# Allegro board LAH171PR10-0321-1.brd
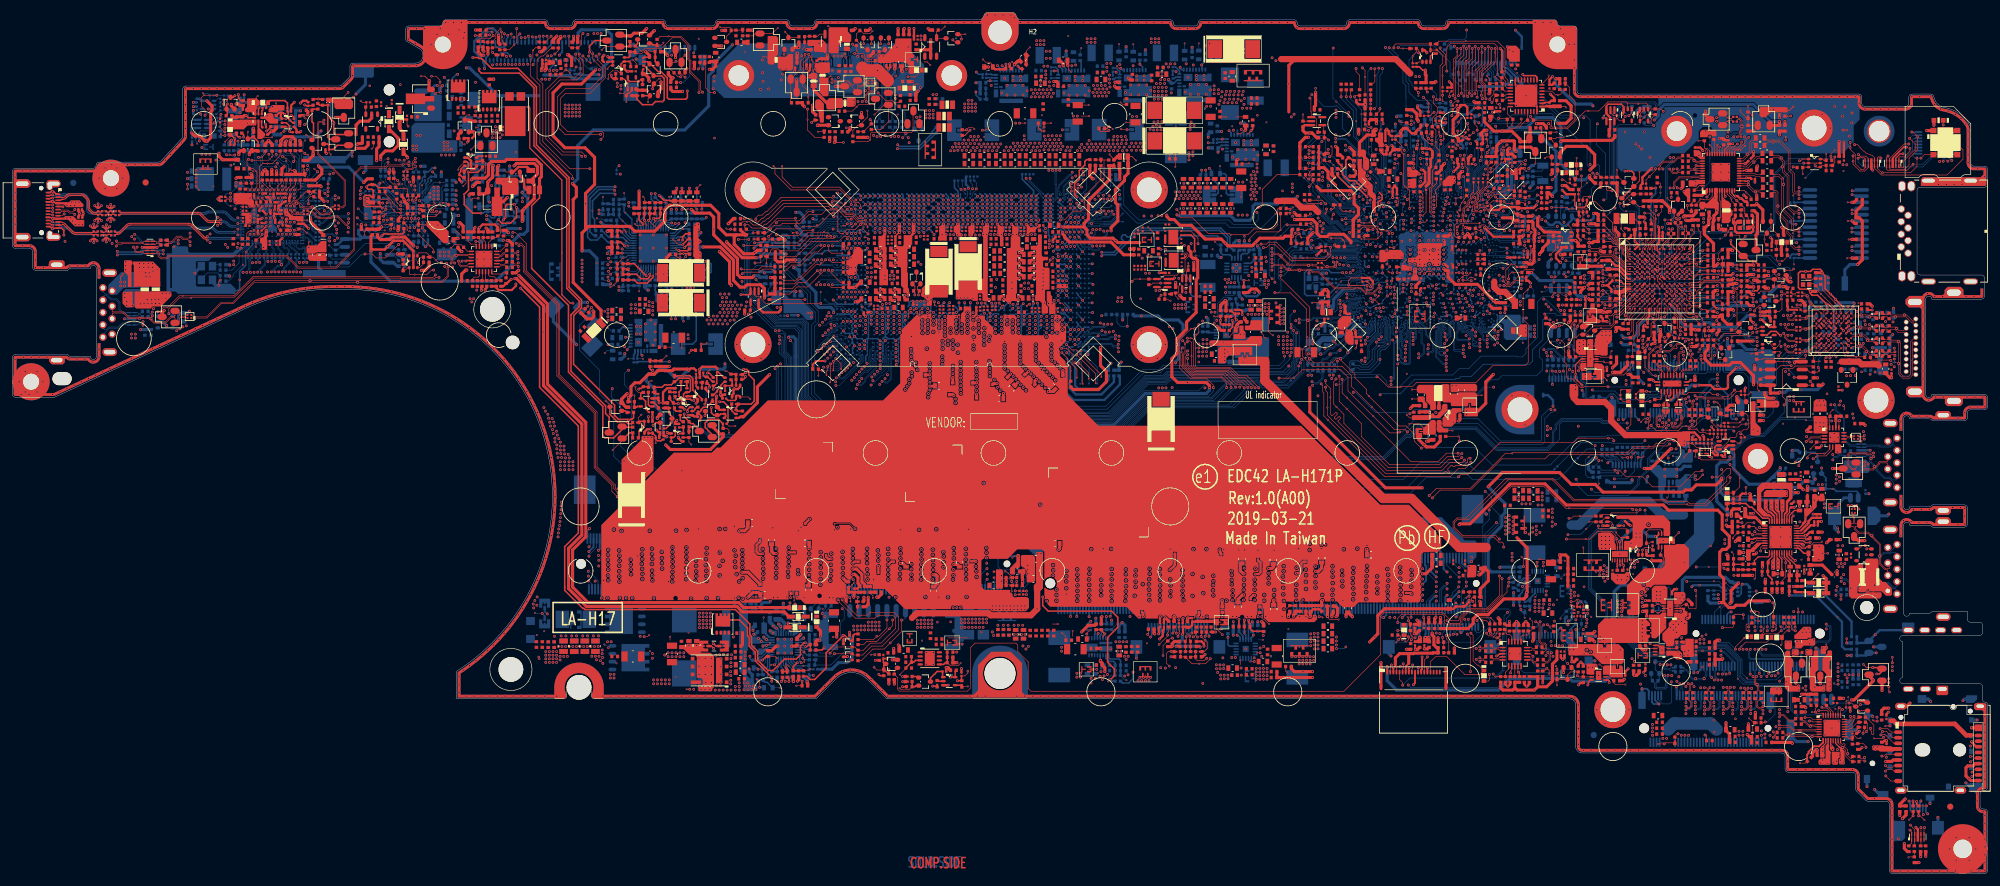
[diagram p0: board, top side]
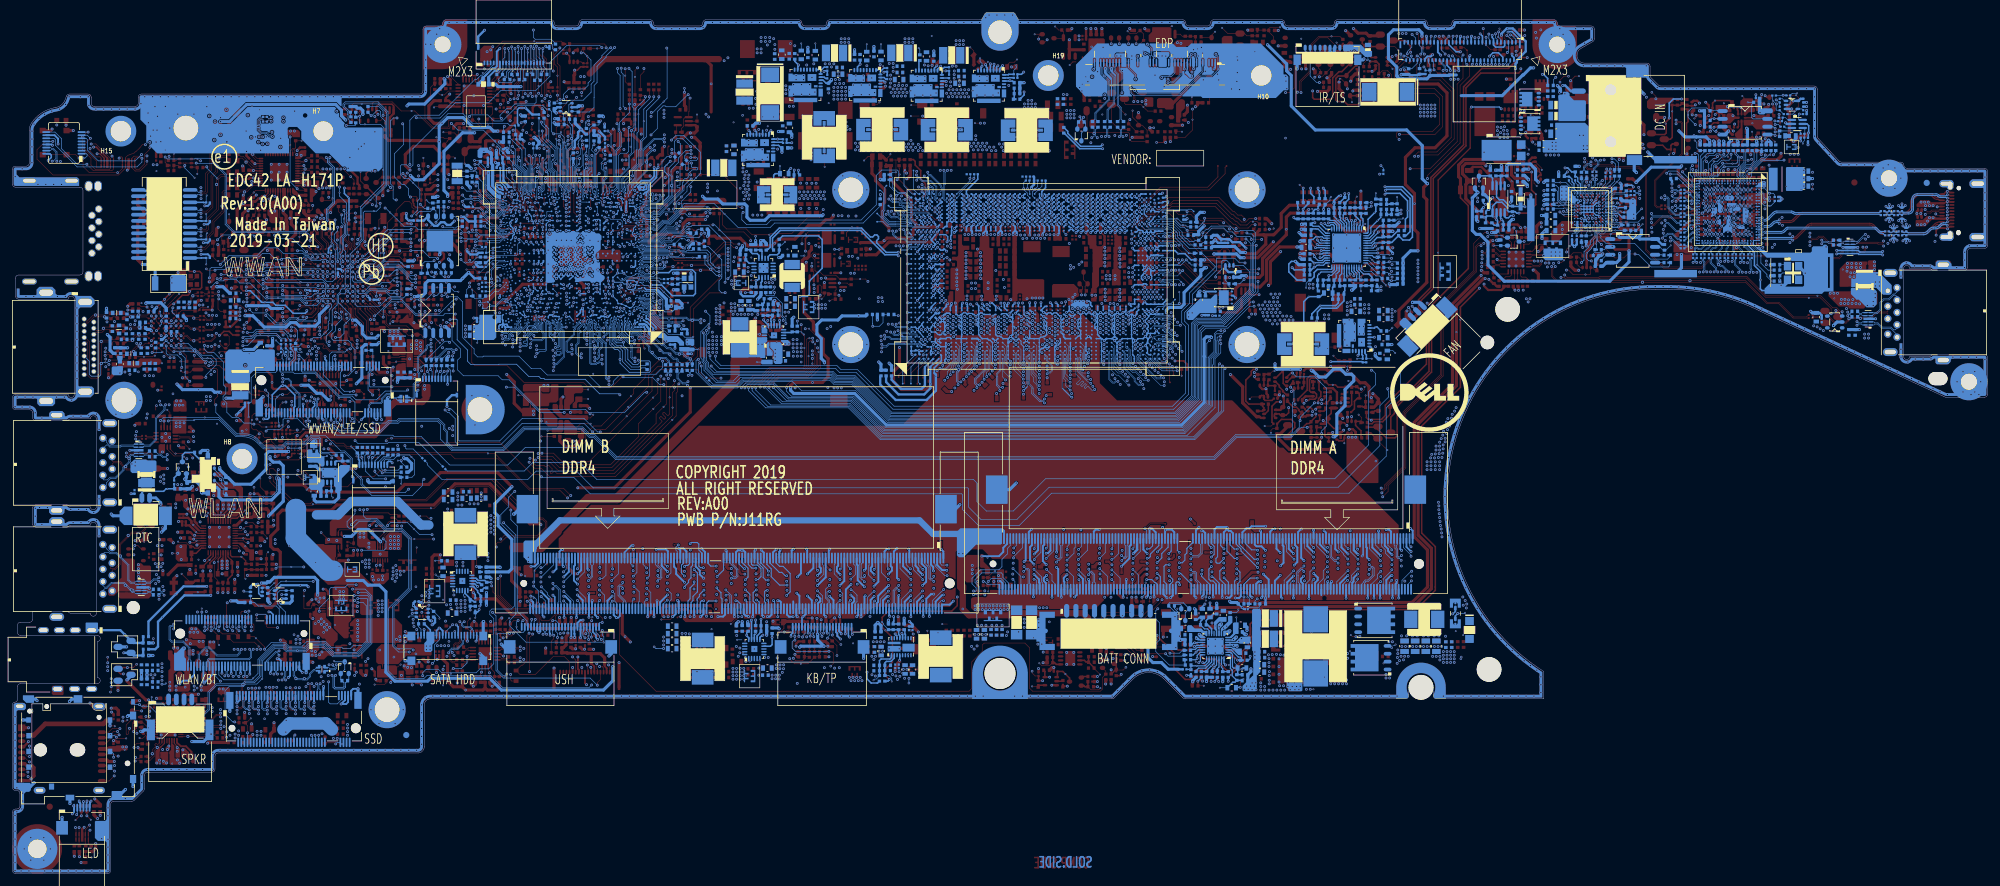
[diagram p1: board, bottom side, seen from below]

Outline 319.05 x 139.2 mm; copper layers: TOP, GND1, IN1, VCC, IN2, IN3, GND2, IN4, GND3, BOTTOM. Coordinates in mm from the lower left corner of the outline.

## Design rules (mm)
net group DDR_A_CLK0: nets DDR_A_CLK0 DDR_A_CLK#0
net group DDR_A_CLK1: nets DDR_A_CLK1 DDR_A_CLK#1
net group DDR_A_DQS0: nets DDR_A_DQS0 DDR_A_DQS#0
net group DDR_A_DQS1: nets DDR_A_DQS1 DDR_A_DQS#1
net group DDR_A_DQS2: nets DDR_A_DQS2 DDR_A_DQS#2
net group DDR_A_DQS3: nets DDR_A_DQS3 DDR_A_DQS#3
net group DDR_A_DQS4: nets DDR_A_DQS4 DDR_A_DQS#4
net group DDR_A_DQS5: nets DDR_A_DQS5 DDR_A_DQS#5
net group DDR_A_DQS6: nets DDR_A_DQS6 DDR_A_DQS#6
net group DDR_A_DQS7: nets DDR_A_DQS7 DDR_A_DQS#7
net group DDR_ALERT: nets DDR_A_ALERT# DDR_B_ALERT#
net group DDR_B_CLK0: nets DDR_B_CLK0 DDR_B_CLK#0
net group DDR_B_CLK1: nets DDR_B_CLK1 DDR_B_CLK#1
net group DDR_B_DQS0: nets DDR_B_DQS0 DDR_B_DQS#0
net group DDR_B_DQS1: nets DDR_B_DQS1 DDR_B_DQS#1
net group DDR_B_DQS2: nets DDR_B_DQS2 DDR_B_DQS#2
net group DDR_B_DQS3: nets DDR_B_DQS3 DDR_B_DQS#3
net group DDR_B_DQS4: nets DDR_B_DQS4 DDR_B_DQS#4
net group DDR_B_DQS6: nets DDR_B_DQS6 DDR_B_DQS#6
net group DDR_B_DQS7: nets DDR_B_DQS7 DDR_B_DQS#7
net group DDR_REST: nets DDR4_DRAMRST#_PCH DDR_DRAMRST#
net group DDRA_CKE: nets DDR_A_CKE0 DDR_A_CKE1
net group DDRB_CKE: nets DDR_B_CKE0 DDR_B_CKE1
net group SD_1_DAT0: nets SD_1_DAT0 SD_1_DAT1
net group SD_1_DAT0_R: nets SD_1_DAT0_R SD_1_DAT1_R
net group TBTA_LS: nets TBTA_LSRX TBTA_LSTX
net group TBTA_SBU: nets TBTA_SBU1 TBTA_SBU2
net group UPD1_SMBCLK: nets UPD1_SMBCLK UPD1_SMBDAT
net group UPD1_SMBCLK_Q: nets UPD1_SMBCLK_Q UPD1_SMBDAT_Q
net group VSSMPHY_SENSE: nets VCCMPHY_SENSE VSSMPHY_SENSE
net group 5: nets ESPI_ALERT# ESPI_CS# ESPI_IO0 ESPI_IO0_R ESPI_IO1 ESPI_IO1_R ESPI_IO2 ESPI_IO2_R ESPI_IO3 ESPI_IO3_R ESPI_RESET# PCH_SPI_CS#0 PCH_SPI_CS#0_R1 PCH_SPI_CS#0_R2 PCH_SPI_CS#1 PCH_SPI_CS#1_R1 PCH_SPI_CS#1_R3 PCH_SPI_CS#2 PCH_SPI_CS#2_R PCH_SPI_D0 PCH_SPI_D0_0_R PCH_SPI_D0_1_R PCH_SPI_D0_2_R PCH_SPI_D0_R1 PCH_SPI_D1 PCH_SPI_D1_0_R PCH_SPI_D1_1_R PCH_SPI_D1_2_R PCH_SPI_D1_R1 PCH_SPI_D2 PCH_SPI_D2_0_R PCH_SPI_D2_1_R PCH_SPI_D2_R1 PCH_SPI_D2_XDP PCH_SPI_D3 PCH_SPI_D3_0_R PCH_SPI_D3_1_R PCH_SPI_D3_R1
net group 10: nets H_THERMTRIP# PCH_RTCRST# SYS_RESET#
net group 12: nets BC_CLK_ECE1117 BC_DAT_ECE1117 PCIECOMP PCIECOMP# SD_1_CLK SD_1_CLK_R
net group 14: nets I2C1_SCK_TP
net group 15: nets AUD_AZACPU_SCLK AUD_AZACPU_SCLK_R CLK_TP_SIO_R CPU_XDP_TCLK DAT_TP_SIO_I2C_CLK DAT_TP_SIO_R DMIC_CLK0 DMIC_CLK_CODEC DPSNK0_DDC_CLK ESPI_CLK ESPI_CLK_5105 GPU_SMCLK HDA_BIT_CLK HDA_BIT_CLK_R I2C0_SCL_TS I2C1_SCK_TP_R LSPCON_CLK MEM_SMBCLK MSCLK PBAT_CHARGER_SMBCLK PBAT_SMBCLK_C PCH_CL_CLK1 PCH_CL_DATA1 PCH_CL_RST1# PCH_DP1_CTRL_CLK PCH_DP3_CTRL_CLK PCH_JTAGX PCH_SPI_CLK PCH_SPI_CLK_0_R PCH_SPI_CLK_1_R PCH_SPI_CLK_2_R PCH_SPI_CLK_R1 PCI_CLK_LPC1 PCIE_WAKE#_AR PCIE_WAKE#_AR_R SCL_CHG SML0_SMBCLK SML1_SMBCLK SUSCLK SUSCLK_R SVID_ALERT#_PWR_CPU SVID_DAT_PWR_CPU TBT_I2C_SCL TBT_ROM_CLK TBT_RTD3_WAKE# TBT_RTD3_WAKE#_GPD7 TBT_RTD3_WAKE#_K18 TBTA_ROM_CLK_PD TBTA_ROM_CLK_PD_R USB2_COMP WIGIG_32KHZ
net group 20: nets HDMI_CLK_27M_IN HDMI_CLK_27M_OUT HDMI_CLK_27M_OUT_R MEC_XTAL1 MEC_XTAL2 MEC_XTAL2_R PCH_RTCX1 PCH_RTCX1_R PCH_RTCX2 REFCLK_CNV XCLK_RBIAS XTAL24_IN XTAL24_IN_R1 XTAL24_OUT XTAL24_OUT_R1 XTAL_25_IN XTAL_25_IN_R XTAL_25_OUT XTAL_25_OUT_R XTALI XTALO XTALO_R
net group 25: nets EDP_COMP
net group CARD READER: nets SD_1_N0 SD_1_N1 SD_1_P0 SD_1_P1
net group CNVI: nets CLK_CNV_PRX_DTX_N CLK_CNV_PRX_DTX_P CLK_CNV_PTX_DRX_N CLK_CNV_PTX_DRX_P CNV_PRX_DTX_N0 CNV_PRX_DTX_N1 CNV_PRX_DTX_P0 CNV_PRX_DTX_P1 CNV_PTX_DRX_N0 CNV_PTX_DRX_N1 CNV_PTX_DRX_P0 CNV_PTX_DRX_P1
net group DDR_RCOMP: nets DDR_RCOMP0 DDR_RCOMP1 DDR_RCOMP2
net group DDR_XDP_WAN_SMBCLK: nets DDR_XDP_WAN_SMBDAT
net group DDRA_CMD: nets DDR_A_ACT# DDR_A_BA0 DDR_A_BA1 DDR_A_BG0 DDR_A_BG1 DDR_A_MA0 DDR_A_MA1 DDR_A_MA2 DDR_A_MA3 DDR_A_MA4 DDR_A_MA5 DDR_A_MA6 DDR_A_MA7 DDR_A_MA8 DDR_A_MA9 DDR_A_MA10 DDR_A_MA11 DDR_A_MA12 DDR_A_MA13 DDR_A_MA14 DDR_A_MA15 DDR_A_MA16 DDR_A_PAR
net group DDRA_CTL: nets DDR_A_CS#0 DDR_A_CS#1 DDR_A_ODT0 DDR_A_ODT1
net group DDRA_D0: nets DDR_A_D0 DDR_A_D1 DDR_A_D2 DDR_A_D3 DDR_A_D4 DDR_A_D5 DDR_A_D6 DDR_A_D7
net group DDRA_D1: nets DDR_A_D8 DDR_A_D9 DDR_A_D10 DDR_A_D11 DDR_A_D12 DDR_A_D13 DDR_A_D14 DDR_A_D15
net group DDRA_D2: nets DDR_A_D16 DDR_A_D17 DDR_A_D18 DDR_A_D19 DDR_A_D20 DDR_A_D21 DDR_A_D22 DDR_A_D23
net group DDRA_D3: nets DDR_A_D24 DDR_A_D25 DDR_A_D26 DDR_A_D27 DDR_A_D28 DDR_A_D29 DDR_A_D30 DDR_A_D31
net group DDRA_D4: nets DDR_A_D32 DDR_A_D33 DDR_A_D34 DDR_A_D35 DDR_A_D36 DDR_A_D37 DDR_A_D38 DDR_A_D39
net group DDRA_D5: nets DDR_A_D40 DDR_A_D41 DDR_A_D42 DDR_A_D43 DDR_A_D44 DDR_A_D45 DDR_A_D46 DDR_A_D47
net group DDRA_D6: nets DDR_A_D48 DDR_A_D49 DDR_A_D50 DDR_A_D51 DDR_A_D52 DDR_A_D53 DDR_A_D54 DDR_A_D55
net group DDRA_D7: nets DDR_A_D56 DDR_A_D57 DDR_A_D58 DDR_A_D59 DDR_A_D60 DDR_A_D61 DDR_A_D62 DDR_A_D63
net group DDRB_CMD: nets DDR_B_ACT# DDR_B_BA0 DDR_B_BA1 DDR_B_BG0 DDR_B_BG1 DDR_B_MA0 DDR_B_MA1 DDR_B_MA2 DDR_B_MA3 DDR_B_MA4 DDR_B_MA5 DDR_B_MA6 DDR_B_MA7 DDR_B_MA8 DDR_B_MA9 DDR_B_MA10 DDR_B_MA11 DDR_B_MA12 DDR_B_MA13 DDR_B_MA14 DDR_B_MA15 DDR_B_MA16 DDR_B_PAR
net group DDRB_CTL: nets DDR_B_CS#0 DDR_B_CS#1 DDR_B_ODT0 DDR_B_ODT1
net group DDRB_D0: nets DDR_B_D0 DDR_B_D1 DDR_B_D2 DDR_B_D3 DDR_B_D4 DDR_B_D5 DDR_B_D6 DDR_B_D7
net group DDRB_D1: nets DDR_B_D8 DDR_B_D9 DDR_B_D10 DDR_B_D11 DDR_B_D12 DDR_B_D13 DDR_B_D14 DDR_B_D15
net group DDRB_D2: nets DDR_B_D16 DDR_B_D17 DDR_B_D18 DDR_B_D19 DDR_B_D20 DDR_B_D21 DDR_B_D22 DDR_B_D23
net group DDRB_D3: nets DDR_B_D24 DDR_B_D25 DDR_B_D26 DDR_B_D27 DDR_B_D28 DDR_B_D29 DDR_B_D30 DDR_B_D31
net group DDRB_D4: nets DDR_B_D32 DDR_B_D33 DDR_B_D34 DDR_B_D35 DDR_B_D36 DDR_B_D37 DDR_B_D38 DDR_B_D39
net group DDRB_D5: nets DDR_B_D40 DDR_B_D41 DDR_B_D42 DDR_B_D43 DDR_B_D44 DDR_B_D45 DDR_B_D46 DDR_B_D47
net group DDRB_D6: nets DDR_B_D48 DDR_B_D49 DDR_B_D50 DDR_B_D51 DDR_B_D52 DDR_B_D53 DDR_B_D54 DDR_B_D55
net group DDRB_D7: nets DDR_B_D56 DDR_B_D57 DDR_B_D58 DDR_B_D59 DDR_B_D60 DDR_B_D61 DDR_B_D62 DDR_B_D63
net group DMI: nets DMI_CRX_PTX_N0 DMI_CRX_PTX_N1 DMI_CRX_PTX_N2 DMI_CRX_PTX_N3 DMI_CRX_PTX_P0 DMI_CRX_PTX_P1 DMI_CRX_PTX_P2 DMI_CRX_PTX_P3 DMI_CTX_PRX_N0 DMI_CTX_PRX_N1 DMI_CTX_PRX_N2 DMI_CTX_PRX_N3 DMI_CTX_PRX_P0 DMI_CTX_PRX_P1 DMI_CTX_PRX_P2 DMI_CTX_PRX_P3
net group DP: nets CPU_DP1_AUXN CPU_DP1_AUXN_C CPU_DP1_AUXP CPU_DP1_AUXP_C CPU_DP1_N0 CPU_DP1_N0_C CPU_DP1_N1 CPU_DP1_N1_C CPU_DP1_N2 CPU_DP1_N2_C CPU_DP1_N3 CPU_DP1_N3_C CPU_DP1_P0 CPU_DP1_P0_C CPU_DP1_P1 CPU_DP1_P1_C CPU_DP1_P2 CPU_DP1_P2_C CPU_DP1_P3 CPU_DP1_P3_C CPU_DP2_AUXN CPU_DP2_AUXN_C CPU_DP2_AUXP CPU_DP2_AUXP_C CPU_DP2_N0 CPU_DP2_N0_C CPU_DP2_N1 CPU_DP2_N1_C CPU_DP2_N2 CPU_DP2_N2_C CPU_DP2_N3 CPU_DP2_N3_C CPU_DP2_P0 CPU_DP2_P0_C CPU_DP2_P1 CPU_DP2_P1_C CPU_DP2_P2 CPU_DP2_P2_C CPU_DP2_P3 CPU_DP2_P3_C CPU_DP3_AUXN CPU_DP3_AUXN_C CPU_DP3_AUXN_R CPU_DP3_AUXP CPU_DP3_AUXP_C CPU_DP3_AUXP_R CPU_DP3_N0 CPU_DP3_N0_C CPU_DP3_N1 CPU_DP3_N1_C CPU_DP3_N2 CPU_DP3_N2_C CPU_DP3_N3 CPU_DP3_N3_C CPU_DP3_P0 CPU_DP3_P0_C CPU_DP3_P1 CPU_DP3_P1_C CPU_DP3_P2 CPU_DP3_P2_C CPU_DP3_P3 CPU_DP3_P3_C
net group EDP: nets EDP_AUXN EDP_AUXN_C EDP_AUXP EDP_AUXP_C EDP_TXN0 EDP_TXN0_C EDP_TXN1 EDP_TXN1_C EDP_TXP0 EDP_TXP0_C EDP_TXP1 EDP_TXP1_C
net group HDA: nets AUD_AZACPU_SDI AUD_AZACPU_SDI_R AUD_AZACPU_SDO AUD_AZACPU_SDO_R DMIC0 HDA_RST# HDA_RST#_R HDA_SDIN0 HDA_SDIN0_R HDA_SDOUT HDA_SDOUT_R HDA_SYNC HDA_SYNC_R
net group HDMI: nets HDMI_CTRL_CLK HDMI_CTRL_DATA HDMI_L_CLKN HDMI_L_CLKP HDMI_L_TX_N0 HDMI_L_TX_N1 HDMI_L_TX_N2 HDMI_L_TX_P0 HDMI_L_TX_P1 HDMI_L_TX_P2 HDMI_LS_CLKN HDMI_LS_CLKP HDMI_LS_TX_N0 HDMI_LS_TX_N1 HDMI_LS_TX_N2 HDMI_LS_TX_P0 HDMI_LS_TX_P1 HDMI_LS_TX_P2
net group I2C: nets CLK_TP_SIO_I2C_DAT I2C0_SDA_TS I2C1_SDA_TP I2C1_SDA_TP_R TBT_I2C_SDA
net group LAN: nets LAN_MDIN0 LAN_MDIN0_L LAN_MDIN1 LAN_MDIN1_L LAN_MDIN2 LAN_MDIN2_L LAN_MDIN3 LAN_MDIN3_L LAN_MDIP0 LAN_MDIP0_L LAN_MDIP1 LAN_MDIP1_L LAN_MDIP2 LAN_MDIP2_L LAN_MDIP3 LAN_MDIP3_L
net group PCIE: nets PCIE_PRX_C_DTX_N5 PCIE_PRX_C_DTX_N6 PCIE_PRX_C_DTX_P5 PCIE_PRX_C_DTX_P6 PCIE_PRX_C_TTX_N1 PCIE_PRX_C_TTX_N2 PCIE_PRX_C_TTX_N3 PCIE_PRX_C_TTX_N4 PCIE_PRX_C_TTX_P1 PCIE_PRX_C_TTX_P2 PCIE_PRX_C_TTX_P3 PCIE_PRX_C_TTX_P4 PCIE_PRX_DTX_N5 PCIE_PRX_DTX_N6 PCIE_PRX_DTX_N7 PCIE_PRX_DTX_N9 PCIE_PRX_DTX_N10 PCIE_PRX_DTX_N11 PCIE_PRX_DTX_N12 PCIE_PRX_DTX_N17 PCIE_PRX_DTX_N18 PCIE_PRX_DTX_P5 PCIE_PRX_DTX_P6 PCIE_PRX_DTX_P7 PCIE_PRX_DTX_P9 PCIE_PRX_DTX_P10 PCIE_PRX_DTX_P11 PCIE_PRX_DTX_P12 PCIE_PRX_DTX_P17 PCIE_PRX_DTX_P18 PCIE_PRX_L_DTX_N18 PCIE_PRX_L_DTX_P18 PCIE_PRX_SW_DTX_N18 PCIE_PRX_SW_DTX_P18 PCIE_PRX_TTX_N1 PCIE_PRX_TTX_N2 PCIE_PRX_TTX_N3 PCIE_PRX_TTX_N4 PCIE_PRX_TTX_P1 PCIE_PRX_TTX_P2 PCIE_PRX_TTX_P3 PCIE_PRX_TTX_P4 PCIE_PTX_C_DRX_N5 PCIE_PTX_C_DRX_N6 PCIE_PTX_C_DRX_N7 PCIE_PTX_C_DRX_N9 PCIE_PTX_C_DRX_N10 PCIE_PTX_C_DRX_N11 PCIE_PTX_C_DRX_N12 PCIE_PTX_C_DRX_N17 PCIE_PTX_C_DRX_P5 PCIE_PTX_C_DRX_P6 PCIE_PTX_C_DRX_P7 PCIE_PTX_C_DRX_P9 PCIE_PTX_C_DRX_P10 PCIE_PTX_C_DRX_P11 PCIE_PTX_C_DRX_P12 PCIE_PTX_C_DRX_P17 PCIE_PTX_C_SW_DRX_N18 PCIE_PTX_C_SW_DRX_P18 PCIE_PTX_C_TRX_N1 PCIE_PTX_C_TRX_N2 PCIE_PTX_C_TRX_N3 PCIE_PTX_C_TRX_N4 PCIE_PTX_C_TRX_P1 PCIE_PTX_C_TRX_P2 PCIE_PTX_C_TRX_P3 PCIE_PTX_C_TRX_P4 PCIE_PTX_DRX_N5 PCIE_PTX_DRX_N6 PCIE_PTX_DRX_N7 PCIE_PTX_DRX_N9 PCIE_PTX_DRX_N10 PCIE_PTX_DRX_N11 PCIE_PTX_DRX_N12 PCIE_PTX_DRX_N17 PCIE_PTX_DRX_N18 PCIE_PTX_DRX_P5 PCIE_PTX_DRX_P6 PCIE_PTX_DRX_P7 PCIE_PTX_DRX_P9 PCIE_PTX_DRX_P10 PCIE_PTX_DRX_P11 PCIE_PTX_DRX_P12 PCIE_PTX_DRX_P17 PCIE_PTX_DRX_P18 PCIE_PTX_L_DRX_N18 PCIE_PTX_L_DRX_P18 PCIE_PTX_SW_DRX_N18 PCIE_PTX_SW_DRX_P18 PCIE_PTX_TRX_N1 PCIE_PTX_TRX_N2 PCIE_PTX_TRX_N3 PCIE_PTX_TRX_N4 PCIE_PTX_TRX_P1 PCIE_PTX_TRX_P2 PCIE_PTX_TRX_P3 PCIE_PTX_TRX_P4
net group PECI: nets H_PECI PCH_PECI PECI_EC_R
net group PLATFORM CLK: nets CLK_PCIE_N0 CLK_PCIE_N1 CLK_PCIE_N3 CLK_PCIE_N4 CLK_PCIE_N5 CLK_PCIE_N6 CLK_PCIE_P0 CLK_PCIE_P1 CLK_PCIE_P3 CLK_PCIE_P4 CLK_PCIE_P5 CLK_PCIE_P6 CPU_24MHZ_R_D CPU_24MHZ_R_D# PCH_CPU_BCLK_D PCH_CPU_BCLK_D# PCH_CPU_BCLK_R_D PCH_CPU_BCLK_R_D# PCH_CPU_NSSC_CLK_D PCH_CPU_NSSC_CLK_D# PCH_CPU_PCIBCLK_D PCH_CPU_PCIBCLK_D# PCH_CPU_PCIBCLK_R_D PCH_CPU_PCIBCLK_R_D# PCH_XDP_CLK_DN PCH_XDP_CLK_DN_R PCH_XDP_CLK_DP PCH_XDP_CLK_DP_R
net group RJ45: nets RJ45_MDIN0 RJ45_MDIN1 RJ45_MDIN2 RJ45_MDIN3 RJ45_MDIP0 RJ45_MDIP1 RJ45_MDIP2 RJ45_MDIP3
net group S12: nets CPU_2_PCH_TRIGGER CPU_2_PCH_TRIGGER_R DGPU_HOLD_RST# H_CATERR# H_PM_DOWN H_PM_DOWN_R H_PM_SYNC H_PM_SYNC_R H_PROCHOT#_R H_THERMTRIP#_R PCH_2_CPU_TRIGGER PCH_2_CPU_TRIGGER_R PCH_PLTRST# PCH_PLTRST#_AND PCH_TBT_PERST# PCH_THERMTRIP# PLTRST_LAN# PLTRST_TPM# PROCHOT# PROCHOT#_CHG PROCHOT#_R1 TBT_PERST# TBT_PERST#_R TBT_RESET_N_EC TBT_RESET_N_EC_R TBTA_RESET_N_EC_R THERMTRIP1# THERMTRIP2# VCCST_PWRGD VCCST_PWRGD_CPU VRHOT#_CPU XDP_OBS0 XDP_OBS0_R XDP_OBS1 XDP_OBS1_R
net group S15: nets H_VCCST_PWRGD_XDP PCH_DPWROK PCH_DPWROK_EC PCH_INTRUDER_HDR# PCH_PCIE_WAKE# PCH_PWROK PCH_RSMRST# PCH_RSMRST#_AND PCIE_WAKE# PCIE_WAKE#_R SRTCRST# SYS_PWROK
net group S20: nets +DDR_VREF_A_CA +DDR_VREF_B_CA +DDR_VREF_B_DQ +DDR_VREF_CA
net group SATA: nets SATA_PRX_C_DTX_N2 SATA_PRX_C_DTX_P2 SATA_PRX_C_RD_DTX_N2 SATA_PRX_C_RD_DTX_P2 SATA_PRX_DTX_N2 SATA_PRX_DTX_P2 SATA_PRX_RD_DTX_N2 SATA_PRX_RD_DTX_P2 SATA_PTX_C_DRX_N2 SATA_PTX_C_DRX_P2 SATA_PTX_C_RD_DRX_N2 SATA_PTX_C_RD_DRX_P2 SATA_PTX_DRX_N2 SATA_PTX_DRX_P2 SATA_PTX_RD_DRX_N2 SATA_PTX_RD_DRX_P2
net group SD: nets SD_1_CD# SD_1_CMD SD_1_CMD_R SD_1_DAT2 SD_1_DAT2_R SD_1_DAT3 SD_1_DAT3_R
net group SENSE: nets VCC_SENSE_GT VCC_SENSE_IA VCC_SENSE_SA VCCIO_SENSE VSS_SENSE_GT VSS_SENSE_IA VSS_SENSE_SA VSSIO_SENSE
net group SIO: nets H_PWRGD PLTRST_CPU# SIO_EXT_SMI# SIO_EXT_WAKE# SIO_EXT_WAKE#_EC SIO_PWRBTN# SIO_RCIN# SIO_SLP_A# SIO_SLP_LAN# SIO_SLP_S0# SIO_SLP_S3# SIO_SLP_S4#_R SIO_SLP_S5# SIO_SLP_SUS# SIO_SLP_SUS#_R SIO_SLP_WLAN# SYS_PWROK_R XDP_DBRESET#
net group SMB: nets DDR_XDP_WAN_SMBCLK DDR_XDP_WAN_SMBCLK_XDP DDR_XDP_WAN_SMBDAT_XDP SML1_SMBDATA USH_EXPANDER_SMBCLK USH_EXPANDER_SMBDAT
net group SPK: nets INT_SPK_L+ INT_SPK_L- INT_SPK_R+ INT_SPK_R-
net group SVID: nets CPU_VIDALERT# VR_SVID_ALERT# VR_SVID_CLK VR_SVID_DATA
net group TBT: nets TBT_A_TRX_C_DTX_N0 TBT_A_TRX_C_DTX_N1 TBT_A_TRX_C_DTX_P0 TBT_A_TRX_C_DTX_P1 TBT_A_TRX_DTX_N0 TBT_A_TRX_DTX_N1 TBT_A_TRX_DTX_P0 TBT_A_TRX_DTX_P1 TBT_A_TRX_R_DTX_N0 TBT_A_TRX_R_DTX_N1 TBT_A_TRX_R_DTX_P0 TBT_A_TRX_R_DTX_P1 TBT_A_TTX_C_DRX_N0 TBT_A_TTX_C_DRX_N1 TBT_A_TTX_C_DRX_P0 TBT_A_TTX_C_DRX_P1 TBT_A_TTX_DRX_N0 TBT_A_TTX_DRX_N1 TBT_A_TTX_DRX_P0 TBT_A_TTX_DRX_P1 TBT_A_TTX_R_DRX_N0 TBT_A_TTX_R_DRX_N1 TBT_A_TTX_R_DRX_P0 TBT_A_TTX_R_DRX_P1
net group TBT-S: nets SW_TBT_A_USB20_N1 SW_TBT_A_USB20_N1_R SW_TBT_A_USB20_N2 SW_TBT_A_USB20_N2_R SW_TBT_A_USB20_P1 SW_TBT_A_USB20_P1_R SW_TBT_A_USB20_P2 SW_TBT_A_USB20_P2_R TBTA_AUXN TBTA_AUXN_C TBTA_AUXP TBTA_AUXP_C TBTA_LSRX_R TBTA_LSTX_R TBTA_SBU1_R TBTA_SBU2_R
net group THERMAL: nets REM_DIODE1_N REM_DIODE1_P REM_DIODE2_N REM_DIODE2_P REM_DIODE4_N REM_DIODE4_P
net group UART: nets CNV_BRI_PRX_DTX CNV_BRI_PRX_DTX_R CNV_BRI_PTX_DRX CNV_BRI_PTX_DRX_R CNV_RGI_PRX_DTX CNV_RGI_PRX_DTX_R CNV_RGI_PTX_DRX CNV_RGI_PTX_DRX_R ISH_UART0_CTS#_R ISH_UART0_RXD_R ISH_UART0_TXD_R LPSS_UART2_RXD
net group UIM: nets UIM_CLK UIM_DATA UIM_RESET
net group USB20: nets CHR_USB20_N1 CHR_USB20_N1_R CHR_USB20_P1 CHR_USB20_P1_R TBTA_USB20_N TBTA_USB20_N_R TBTA_USB20_P TBTA_USB20_P_R USB20_N1 USB20_N2 USB20_N2_R USB20_N3 USB20_N3_R USB20_N4 USB20_N4_FP USB20_N4_USH USB20_N5 USB20_N6 USB20_N8 USB20_N8_R USB20_N10 USB20_N11 USB20_N11_R USB20_N14 USB20_N14_R USB20_P1 USB20_P2 USB20_P2_R USB20_P3 USB20_P3_R USB20_P4 USB20_P4_FP USB20_P4_USH USB20_P5 USB20_P6 USB20_P8 USB20_P8_R USB20_P10 USB20_P11 USB20_P11_R USB20_P14 USB20_P14_R
net group USB30: nets USB3_PRX_C_RD_DTX_N3 USB3_PRX_C_RD_DTX_P3 USB3_PRX_DTX_N1 USB3_PRX_DTX_N2 USB3_PRX_DTX_N3 USB3_PRX_DTX_N4 USB3_PRX_DTX_P1 USB3_PRX_DTX_P2 USB3_PRX_DTX_P3 USB3_PRX_DTX_P4 USB3_PRX_RD_DTX_N3 USB3_PRX_RD_DTX_P3 USB3_PTX_C_DRX_N1 USB3_PTX_C_DRX_N2 USB3_PTX_C_DRX_N3 USB3_PTX_C_DRX_N4 USB3_PTX_C_DRX_P1 USB3_PTX_C_DRX_P2 USB3_PTX_C_DRX_P3 USB3_PTX_C_DRX_P4 USB3_PTX_C_RD_DRX_N3 USB3_PTX_C_RD_DRX_P3 USB3_PTX_DRX_N1 USB3_PTX_DRX_N2 USB3_PTX_DRX_N3 USB3_PTX_DRX_N4 USB3_PTX_DRX_P1 USB3_PTX_DRX_P2 USB3_PTX_DRX_P3 USB3_PTX_DRX_P4 USB3_PTX_RD_DRX_N3 USB3_PTX_RD_DRX_P3
nets with their own width: min track width 0.254; nets +3.3V_TBT_FLASH_R +COINCELL +RTC_CELL +Z4012 AUD_HP_NB_SENSE AUD_SENSE_A BAT1_LED# BAT1_LED#_R BAT2_LED# BATT_WHITE# BATT_YELLOW# CNV_WT_RCOMP GPPJ_RCOMP PEG_COMP SD_RCOMP_1P8 SD_RCOMP_3P3 TBTA_CC1 TBTA_CC2
nets with their own width: min track width 0.381; nets +3.3V_EC_PLL +LINE1-VREFO-L +LINE1-VREFO-R +VSS_PLL AUD_HP_OUT_L AUD_HP_OUT_L1 AUD_HP_OUT_R AUD_HP_OUT_R1 HP_OUT_L HP_OUT_R LINE1_L LINE1_R
nets with their own width: min track width 0.508; nets +1.0V_ALW_PCH +1.0V_AMPHYPLL +1.0V_AZPLL +1.0V_BCLKPLL2 +1.0V_CLPLLEBB +1.0V_DSW +1.0V_DUSB +1.0V_MPHY +1.0V_OC +1.0V_OCPLL1 +1.0V_PRIM_CNV_HVLO +1.0V_PRIM_FUSE +1.0V_PRIM_XDP +1.0V_SRC +1.0V_VCCSFR +1.0V_VCCSFR_R +1.0V_VCCST +1.0V_VCCST_C +1.0V_VCCSTG +1.0V_VCCSTG_C +1.0V_XTAL +1.0VS_VCCIO +1.2V_LDO +1.2V_LSPCON_VDD +1.2V_LSPCON_VDDA +1.2V_LSPCON_VDDRX +1.2V_LSPCON_VDDTX +1.2V_RUN +1.8V_ALW_VTR3 +1.8V_RUN +1.8V_RUN_CARD +1.8V_RUN_UZ8 +2.8V_FHV0 +2.8V_FHV1 +3.3V_1.8V_AZIO +3.3V_1.8V_GPPA +3.3V_1.8V_GPPD +3.3V_1.8V_SPI +3.3V_ALW +3.3V_ALW2 +3.3V_ALW_UE1 +3.3V_CAM +3.3V_DSW +3.3V_FPBTN +3.3V_FUSE +3.3V_LAN_OUT +3.3V_LSPCON +3.3V_LSPCON_VDD +3.3V_MMI_AUX +3.3V_PGPPBC +3.3V_PGPPEF +3.3V_PGPPG +3.3V_PGPPHK +3.3V_PHVC +3.3V_PUSB2 +3.3V_RTC_LDO +3.3V_RUN +3.3V_RUN_AUDIO +3.3V_RUN_AUDIO_DVDD +3.3V_RUN_AUDIO_IO +3.3V_RUN_DIMM2 +3.3V_SPI +3.3V_TBT_LC +3.3V_TBT_SX +3.3V_TBTA_FLASH +3.3V_TP +3.3V_VDD_DCIN +3.3V_VDD_PIC +3.3V_VPS_UZ12 +5V_ALW +5V_ALW2 +5V_PD_VDD +5V_TBT_VBUS +5V_TBTA_VBUS_D +EC_DEBUG_VCC +RSVD_VCC3P3_1 +RTC_CELL_PCH +SIM_PWR +VCC_FUSEPRG +VCC_SFR_OC +VDDA_AVDD1 GND GNDA
nets with their own width: min track width 0.762; nets +0.9V_LAN +2.5V_MEM +3.3V_VDD_PIC_PDA
nets with their own width: min track width 1.016; nets +3.3V_LAN +3.3V_LAN_UZ2 +3.3V_RUN_CARD +TS_PWR +VHDMI_VCC INT_SPKR_L+ INT_SPKR_L- INT_SPKR_R+ INT_SPKR_R-
nets with their own width: min track width 1.143; nets +3.3V_PHVLDO
nets with their own width: min track width 1.27; nets +1.8V_PRIM +1.8V_PRIM_PCH +3.3V_MMI_IN +MIC2-VREFO RING2 RING2_R SLEEVE SLEEVE_R
nets with their own width: min track width 1.524; nets +3.3V_TBT +3.3V_TBT_S0 +5V_HDD +EDP_VDD +LCDVDD
nets with their own width: min track width 2.032; nets +0.6V_DDR_VTT +3.3V_SSD +BL_PWR_SRC +USB_EX2_PWR +USB_EX3_PWR
nets with their own width: min track width 2.286; nets +3.3V_HDD +3.3V_HDD_M2 +3.3V_WLAN
nets with their own width: min track width 2.54; nets +3.3V_WLAN_UZ4 +5V_RUN_AUDIO +5V_RUN_PVDD_L +5V_USB_CHG_PWR
nets with their own width: min track width 2.794; nets +3.3V_WWAN +3.3V_WWAN_UZ2
nets with their own width: min track width 3.048; nets +5V_ALW_PDA +20V_TBTA_VBUS
nets with their own width: min track width 3.302; nets +3.3V_ALW_PCH +3.3V_ALW_PCH_UZ3
nets with their own width: min track width 4.572; nets +5V_RUN +5V_RUN_UZ4

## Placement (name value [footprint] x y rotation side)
CA1  220P_0402_50V7K  [C_0402]  297.31 30.54 90 bottom
CA2  680P_0402_50V7K  [C_0402]  297.04 37.28 0 bottom
CA3  680P_0402_50V7K  [C_0402]  297.04 35.25 0 bottom
CA4  220P_0402_50V7K  [C_0402]  297.31 33.74 270 bottom
CA5  27P_0402_50V8J  [C_0402]  128.54 124.59 180 top
CA6  82P_0402_50V8J  [C_0402]  125.84 124.59 0 top
CA7  0.1U_0201_10V6K  [C_0201]  128.88 130.76 180 top
CA8  0.1U_0201_10V6K  [C_0201]  289.43 49.72 270 top
CA9  10U_0603_10V6M  [C_0603]  290.38 49.87 270 top
CA10  0.1U_0201_10V6K  [C_0201]  280.67 57.64 90 top
CA12  680P_0402_50V7K  [C_0402]  298.2 30.54 90 bottom
CA13  680P_0402_50V7K  [C_0402]  298.2 32.83 90 bottom
CA19  1000P_0402_50V7K  [C_0402]  283.21 60.21 90 top
CA22  1000P_0402_50V7K  [C_0402]  285.87 60.21 90 top
CA23  1000P_0402_50V7K  [C_0402]  284.98 60.21 90 top
CA24  1000P_0402_50V7K  [C_0402]  284.09 60.21 90 top
CA25  10U_0603_10V6M  [C_0603]  285.87 48.46 180 top
CA27  0.1U_0402_25V6  [C_0402]  281.36 49.16 90 top
CA28  0.1U_0402_25V6  [C_0402]  279.51 50 0 top
CA29  1U_0201_6.3V6K  [C_0201]  292.1 58.1 270 top
CA31  1U_0201_6.3V6M  [C_0201]  279.01 59.84 90 top
CA33  10P_0402_50V8J  [C_0402]  278.71 55.14 180 top
CA35  2.2U_0402_6.3V6M  [C_0402]  290.24 52.86 0 top
CA41  0.1U_0402_25V6  [C_0402]  283.6 50.24 180 top
CA43  10U_0603_10V6M  [C_0603]  288.41 49.62 270 top
CA44  10U_0603_10V6M  [C_0603]  287.14 49.62 270 top
CA45  0.1U_0201_10V6K  [C_0201]  287.36 61.59 0 top
CA46  10U_0603_10V6M  [C_0603]  282.13 60.6 180 top
CA47  0.1U_0201_10V6K  [C_0201]  281.97 59.71 180 top
CA48  10U_0603_10V6M  [C_0603]  287.21 62.63 0 top
CA49  1U_0201_6.3V6K  [C_0201]  291.63 56.28 180 top
CA51  10U_0603_10V6M  [C_0603]  290.13 51.78 0 top
CA52  10U_0603_10V6M  [C_0603]  288.67 58.7 90 top
CA53  10U_0603_10V6M  [C_0603]  280.35 54.06 180 top
CA54  100P_0402_50V8J  [C_0402]  278.71 56.09 180 top
CA55  0.1U_0201_10V6K  [C_0201]  281.17 52.19 270 top
CA56  10U_0603_10V6M  [C_0603]  280.35 51.9 180 top
CA57  0.1U_0201_10V6K  [C_0201]  287.27 59.2 90 top
CA58  10U_0603_10V6M  [C_0603]  289.87 58.7 90 top
CA59  10U_0603_10V6M  [C_0603]  289.81 64.84 270 top
CA60  0.1U_0201_10V6K  [C_0201]  288.86 64.88 270 top
CA61  10U_0603_10V6M  [C_0603]  279.92 57.94 180 top
CA62  100P_0402_50V8J  [C_0402]  278.01 50 180 top
CA63  12P_0402_50V8J  [C_0402]  288.03 64.62 270 top
CA64  68P_0402_50V8J  [C_0402]  287.14 64.62 270 top
CA65  12P_0402_50V8J  [C_0402]  261.87 33.68 270 top
CA66  68P_0402_50V8J  [C_0402]  262.76 33.68 270 top
CA67  12P_0402_50V8J  [C_0402]  281.29 73.23 0 top
CA68  68P_0402_50V8J  [C_0402]  281.29 74.11 0 top
CA69  33P_0402_50V8J  [C_0402]  291.14 61.03 90 top
CA72  100P_0402_50V8J  [C_0402]  280.41 49.12 270 top
CA73  2P_0402_50V8C  [C_0402]  218.38 120.28 180 top
CA74  2P_0402_50V8C  [C_0402]  221.24 121.87 180 top
CA75  2P_0402_50V8C  [C_0402]  218.49 121.87 0 top
CA76  2P_0402_50V8C  [C_0402]  219.4 125.04 180 top
CA77  330P_0402_50V8J  [C_0402]  290.37 54.25 0 top
CA78  330P_0402_50V8J  [C_0402]  290.75 55.19 0 top
CA79  1U_0201_6.3V6K  [C_0201]  291.46 58.1 270 top
CA80  1U_0201_6.3V6K  [C_0201]  291.63 56.92 180 top
CC28  0.1U_0402_25V6  [C_0402]  89.42 131.52 0 top
CC29  0.1U_0402_25V6  [C_0402]  89.42 130.63 0 top
CC32  0.1U_0201_10V6K  [C_0201]  90.8 129.82 270 bottom
CC33  0.1U_0402_25V6  [C_0402]  90.42 133.47 90 top
CC81  22U_0603_6.3V6M  [C_0603]  150.41 78.83 180 top
CC82  22U_0603_6.3V6M  [C_0603]  167.39 79.22 315 top
CC83  22U_0603_6.3V6M  [C_0603]  158.66 76.78 0 top
CC84  22U_0603_6.3V6M  [C_0603]  160.9 77.94 45 top
CC161  10U_0402_6.3V6M  [C_0402]  155.74 75.94 90 top
CC163  10U_0402_6.3V6M  [C_0402]  164.15 80.01 135 top
CC164  10U_0402_6.3V6M  [C_0402]  154.2 79.32 0 top
CC165  10U_0402_6.3V6M  [C_0402]  150.47 77.42 0 top
CC166  10U_0402_6.3V6M  [C_0402]  151.89 78.4 90 top
CC167  10U_0402_6.3V6M  [C_0402]  165.8 78.41 135 top
CC168  10U_0402_6.3V6M  [C_0402]  160.07 79.57 45 top
CC170  10U_0402_6.3V6M  [C_0402]  157.44 79.07 0 top
CC171  10U_0402_6.3V6M  [C_0402]  146.54 80.59 0 top
CC172  10U_0402_6.3V6M  [C_0402]  154.08 91.34 180 top
CC185  10U_0402_6.3V6M  [C_0402]  169.67 79.63 90 top
CC186  1U_0201_6.3V6M  [C_0201]  181.22 97.64 90 top
CC187  10U_0402_6.3V6M  [C_0402]  168.97 95.84 270 top
CC188  10U_0402_6.3V6M  [C_0402]  168.07 97.36 180 top
CC189  10U_0402_6.3V6M  [C_0402]  168.07 96.47 180 top
CC191  1U_0201_6.3V6M  [C_0201]  182.56 104.43 270 top
CC192  1U_0201_6.3V6M  [C_0201]  169.07 102.94 180 top
CC193  1U_0201_6.3V6M  [C_0201]  181.24 103.44 270 top
CC194  1U_0201_6.3V6M  [C_0201]  181.81 104 270 top
CC195  1U_0201_6.3V6M  [C_0201]  181.8 97.64 90 top
CC209  1U_0201_6.3V6M  [C_0201]  137.54 90.69 0 top
CC210  1U_0201_6.3V6M  [C_0201]  125.77 90.27 90 bottom
CC269  0.1U_0402_25V6  [C_0402]  87.32 133.45 90 top
CC272  10U_0402_6.3V6M  [C_0402]  168.07 95.58 180 top
CC300  100P_0402_50V8J  [C_0402]  129.17 103.2 180 bottom
CC301  100P_0402_50V8J  [C_0402]  178.42 90.37 0 bottom
CC302  0.1U_0402_25V6  [C_0402]  211.91 118.95 180 top
CC303  0.1U_0402_25V6  [C_0402]  208.58 103.53 0 bottom
CC304  0.1U_0402_25V6  [C_0402]  208.33 101.86 0 top
CC305  0.1U_0402_25V6  [C_0402]  212.16 101.67 180 bottom
CC306  0.1U_0402_25V6  [C_0402]  91.75 130.11 270 bottom
CC307  0.1U_0402_25V6  [C_0402]  85.97 134.39 270 top
CC308  0.1U_0402_25V6  [C_0402]  93.52 130.08 270 bottom
CC310  0.1U_0201_10V6K  [C_0201]  221.94 116.25 0 top
CC311  0.1U_0201_10V6K  [C_0201]  212.85 86.09 270 bottom
CC316  33P_0402_50V8J  [C_0402]  248.85 82.1 90 bottom
CC318  33P_0402_50V8J  [C_0402]  228.44 116.49 270 bottom
CC319  33P_0402_50V8J  [C_0402]  228.39 119.83 0 top
CC320  33P_0402_50V8J  [C_0402]  229.92 121.08 0 bottom
CC322  2.2P_0402_50V8C  [C_0402]  126.34 92.45 90 bottom
CC323  0.1U_0402_25V6  [C_0402]  174.94 115.4 270 top
CC324  0.1U_0402_25V6  [C_0402]  126.29 102.88 180 bottom
CC325  33P_0402_50V8J  [C_0402]  117.61 105.86 180 top
CC327  2.2P_0402_50V8C  [C_0402]  222.11 117.04 0 top
CC328  2.2P_0402_50V8C  [C_0402]  240.28 92.29 270 top
CC329  0.1U_0201_10V6K  [C_0201]  221.19 118.41 0 top
CC330  0.1U_0201_10V6K  [C_0201]  209.99 84.6 270 bottom
CC331  0.1U_0201_10V6K  [C_0201]  216.37 87.32 0 top
CC332  0.1U_0201_10V6K  [C_0201]  217.8 86.14 90 top
CC333  22U_0603_6.3V6M  [C_0603]  178.81 114.63 0 top
CC334  0.1U_0201_10V6K  [C_0201]  86.2 130.88 180 top
CC335  0.1U_0201_10V6K  [C_0201]  86.2 131.52 180 top
CC336  0.1U_0201_10V6K  [C_0201]  123.82 101.95 90 bottom
CC337  0.1U_0201_10V6K  [C_0201]  122.68 101.95 90 bottom
CC500  10U_0402_6.3V6M  [C_0402]  168.07 94.69 180 top
CC501  10U_0402_6.3V6M  [C_0402]  168.91 98.17 90 top
CC549  0.1U_0201_10V6K  [C_0201]  129.92 106.28 270 bottom
CC556  0.1U_0201_10V6K  [C_0201]  241.93 114.91 90 top
CC557  0.1U_0201_10V6K  [C_0201]  182.37 98.22 270 top
CC558  0.1U_0201_10V6K  [C_0201]  182.94 98.22 270 top
CC568  22U_0603_6.3V6M  [C_0603]  127.4 93.44 270 bottom
CC569  22U_0603_6.3V6M  [C_0603]  184.22 100.67 180 top
CD1  10U_0603_6.3V6M  [C_0603]  148.78 44.99 90 top
CD2  10U_0603_6.3V6M  [C_0603]  120.2 56.68 180 top
CD3  10U_0603_6.3V6M  [C_0603]  122.61 54.64 270 top
CD4  10U_0603_6.3V6M  [C_0603]  122.23 45.06 180 top
CD5  10U_0603_6.3V6M  [C_0603]  128.58 45.16 90 top
CD6  10U_0603_6.3V6M  [C_0603]  127.31 53.37 0 top
CD7  10U_0603_6.3V6M  [C_0603]  153 51 270 top
CD8  10U_0603_6.3V6M  [C_0603]  144.36 51 270 top
CD9  1U_0201_10V6M  [C_0201]  126.95 51.91 180 top
CD10  1U_0201_10V6M  [C_0201]  154.9 51.08 270 top
CD11  1U_0201_10V6M  [C_0201]  128.08 55.96 90 top
CD12  1U_0201_10V6M  [C_0201]  120.77 54.47 270 top
CD13  1U_0201_10V6M  [C_0201]  136.69 51.01 270 top
CD14  1U_0201_10V6M  [C_0201]  131.44 52.03 270 top
CD15  1U_0201_10V6M  [C_0201]  139.89 48.03 90 top
CD16  1U_0201_10V6M  [C_0201]  142.38 51.01 270 top
CD17  1U_0201_10V6M  [C_0201]  165.55 48.84 180 top
CD18  1U_0201_10V6M  [C_0201]  165.55 49.79 180 top
CD19  10U_0603_6.3V6M  [C_0603]  166.01 50.87 180 top
CD20  10U_0603_6.3V6M  [C_0603]  165.67 47.64 180 top
CD21  330U_D3_2.5VY_R6M  [C_D3]  100.01 58.02 90 top
CD22  10U_0603_6.3V6M  [C_0603]  159.19 46.58 180 top
CD23  1U_0201_10V6M  [C_0201]  159.14 48.8 180 top
CD24  1U_0201_10V6M  [C_0201]  159.14 47.85 180 top
CD25  0.1U_0201_6.3V6K  [C_0201]  135.95 45.49 90 top
CD26  2.2U_0402_6.3V6M  [C_0402]  136.84 45.49 90 top
CD27  2.2U_0402_6.3V6M  [C_0402]  162.44 49.92 0 top
CD28  0.1U_0201_10V6K  [C_0201]  162.55 50.68 0 top
CD29  0.1U_0402_25V6  [C_0402]  120.13 43.6 0 bottom
CD31  0.022U_0402_16V7K  [C_0402]  138.55 46.4 270 top
CD32  0.1U_0402_25V6  [C_0402]  121.68 46.77 180 top
CD33  10U_0603_6.3V6M  [C_0603]  211.48 51.68 270 top
CD34  10U_0603_6.3V6M  [C_0603]  220.18 51.56 180 top
CD35  10U_0603_6.3V6M  [C_0603]  215.74 43.62 270 top
CD36  10U_0603_6.3V6M  [C_0603]  197.99 42.43 90 top
CD37  10U_0603_6.3V6M  [C_0603]  203.74 42.03 90 top
CD38  10U_0603_6.3V6M  [C_0603]  203.67 51.43 270 top
CD39  10U_0603_6.3V6M  [C_0603]  198.59 51.56 270 top
CD40  10U_0603_6.3V6M  [C_0603]  167.76 53.35 0 top
CD41  1U_0201_10V6M  [C_0201]  200.02 43.79 90 top
CD42  1U_0201_10V6M  [C_0201]  225.1 44.78 90 top
CD43  1U_0201_10V6M  [C_0201]  201.2 51.32 270 top
CD44  1U_0201_10V6M  [C_0201]  208.88 51 270 top
CD45  1U_0201_10V6M  [C_0201]  195.87 51.62 180 top
CD46  1U_0201_10V6M  [C_0201]  187.76 52.28 270 top
CD47  1U_0201_10V6M  [C_0201]  192.25 42.29 180 top
CD48  1U_0201_10V6M  [C_0201]  181.88 42.29 0 top
CD49  330U_D3_2.5VY_R6M  [C_D3]  185.54 70.28 90 top
CD50  1U_0201_10V6M  [C_0201]  232.74 50.62 270 top
CD51  1U_0201_10V6M  [C_0201]  234.64 50.61 270 top
CD52  10U_0603_6.3V6M  [C_0603]  230.72 51.43 180 top
CD53  10U_0603_6.3V6M  [C_0603]  230.72 50.16 180 top
CD54  10U_0603_6.3V6M  [C_0603]  232.09 42.81 90 top
CD55  1U_0201_10V6M  [C_0201]  234.31 43.18 90 top
CD56  1U_0201_10V6M  [C_0201]  233.17 43.18 90 top
CD57  0.1U_0201_6.3V6K  [C_0201]  210.53 43.32 270 top
CD58  2.2U_0402_6.3V6M  [C_0402]  211.48 43.32 270 top
CD59  2.2U_0402_6.3V6M  [C_0402]  235.24 48.19 180 top
CD60  0.1U_0201_10V6K  [C_0201]  235.27 48.95 180 top
CD61  0.1U_0402_25V6  [C_0402]  195.42 42.21 90 top
CD62  0.022U_0402_16V7K  [C_0402]  207.23 42.4 90 top
CE3  2200P_0402_50V7K  [C_0402]  258.05 92.91 0 top
CE4  2200P_0402_50V7K  [C_0402]  256.6 112.55 270 top
CE8  .047U_0402_16V7K  [C_0402]  279.26 94.94 0 top
CE10  0.1U_0201_10V6K  [C_0201]  263.88 111.52 180 top
CE11  0.1U_0201_10V6K  [C_0201]  262.04 103.21 180 top
CE12  2.2U_0402_6.3V6M  [C_0402]  263.01 109.85 90 top
CE13  0.1U_0201_10V6K  [C_0201]  261.29 92.76 180 bottom
CE14  1U_0201_10V6M  [C_0201]  265.97 103.05 0 top
CE15  0.1U_0201_10V6K  [C_0201]  259.01 95.88 180 top
CE16  10U_0402_6.3V6M  [C_0402]  251.68 100.1 180 top
CE17  22U_0603_6.3V6M  [C_0603]  257.76 99.11 270 top
CE18  0.1U_0201_10V6K  [C_0201]  258.99 98.26 270 top
CE19  0.1U_0201_10V6K  [C_0201]  280.73 90.35 270 top
CE20  0.1U_0201_10V6K  [C_0201]  266.47 97.14 90 bottom
CE21  0.1U_0201_10V6K  [C_0201]  264.14 88.91 270 top
CE22  0.1U_0201_10V6K  [C_0201]  256.31 89.29 0 top
CE23  0.1U_0201_10V6K  [C_0201]  265.97 103.68 0 top
CE24  2200P_0402_50V7K  [C_0402]  268.37 103.43 180 top
CE25  0.1U_0201_10V6K  [C_0201]  270.34 94.18 0 bottom
CE26  2200P_0402_50V7K  [C_0402]  269.52 105.21 180 top
CE27  2200P_0402_50V7K  [C_0402]  270.72 103.49 180 top
CE28  12P_0402_50V8J  [C_0402]  260.38 103.21 180 top
CE29  12P_0402_50V8J  [C_0402]  262.82 105.22 90 top
CE30  1U_0201_10V6M  [C_0201]  276.18 96.72 0 top
CE31  1U_0201_10V6M  [C_0201]  258.87 94.03 180 top
CE32  10U_0402_6.3V6M  [C_0402]  92.39 88.34 225 top
CE35  100P_0402_50V8J  [C_0402]  146.48 94.18 180 top
CE36  0.1U_0402_25V6  [C_0402]  284.74 89.99 180 top
CE37  100P_0402_50V8J  [C_0402]  265.82 31.19 180 bottom
CE38  0.1U_0402_25V6  [C_0402]  273.86 100.78 0 top
CE39  100P_0402_50V8J  [C_0402]  146.84 121.49 180 bottom
CE40  4700P_0402_25V7K  [C_0402]  276.21 95.07 0 top
CE46  100P_0402_50V8J  [C_0402]  131.35 43.28 0 bottom
CE47  4700P_0402_25V7K  [C_0402]  274.77 88.78 270 top
CE52  0.1U_0402_25V6K  [C_0402]  258.83 119.26 180 top
CE53  0.1U_0402_25V6K  [C_0402]  258.83 120.22 180 top
CE54  10P_0402_50V8J  [C_0402]  255.14 98.11 90 bottom
CE57  33P_0402_50V8J  [C_0402]  282.05 96.59 0 top
CE59  12P_0402_50V8J  [C_0402]  253.87 100.52 90 top
CE60  68P_0402_50V8J  [C_0402]  276.21 90.24 0 top
CE61  68P_0402_50V8J  [C_0402]  252.93 100.5 90 top
CE62  4700P_0402_25V7K  [C_0402]  255.67 99.17 180 top
CE63  1U_0201_10V6M  [C_0201]  284.16 100.75 90 top
CE64  0.1U_0402_25V6  [C_0402]  286.71 99.96 180 top
CE65  22P_0402_50V8J  [C_0402]  285.22 103.2 0 top
CE66  0.1U_0402_25V6  [C_0402]  264.26 86.42 0 top
CE548  0.1U_0201_10V6K  [C_0201]  252.37 94.75 0 top
CE549  0.1U_0201_10V6K  [C_0201]  252.95 109.8 180 top
CH2  100P_0402_50V8J  [C_0402]  212.53 92.39 90 top
CH4  15P_0402_50V8J  [C_0402]  245.61 111.76 90 bottom
CH5  15P_0402_50V8J  [C_0402]  245.61 114.45 270 bottom
CH9  0.1U_0201_10V6K  [C_0201]  253.64 105.55 0 bottom
CH10  0.1U_0402_25V6  [C_0402]  211.21 123.45 180 top
CH13  15P_0402_50V8J  [C_0402]  211.58 95.27 270 bottom
CH14  15P_0402_50V8J  [C_0402]  211.58 96.14 90 bottom
CH20  1U_0201_6.3V6M  [C_0201]  216.43 86.75 0 top
CH21  1U_0201_6.3V6M  [C_0201]  222.36 110.22 0 top
CH22  4.7U_0402_6.3V6M  [C_0402]  222.36 111.11 0 top
CH29  1U_0201_6.3V6M  [C_0201]  212.5 89.67 180 top
CH30  4.7U_0402_6.3V6M  [C_0402]  215.78 115.71 180 top
CH31  1U_0201_6.3V6M  [C_0201]  212.02 86.13 270 bottom
CH32  4.7U_0402_6.3V6M  [C_0402]  215.26 89.79 90 top
CH33  1U_0201_6.3V6M  [C_0201]  242.91 113.8 0 top
CH34  1U_0201_6.3V6M  [C_0201]  228.13 94.63 180 top
CH35  1U_0201_6.3V6M  [C_0201]  239.89 114.82 0 bottom
CH36  1U_0201_6.3V6M  [C_0201]  230.74 101.65 0 top
CH37  1U_0402_6.3VAK  [C_0402]  217.62 112.72 180 top
CH38  0.1U_0201_10V6K  [C_0201]  227.55 96.21 180 top
CH40  1U_0201_6.3V6M  [C_0201]  244.34 107.57 90 top
CH41  1U_0201_6.3V6M  [C_0201]  241.68 111.08 270 top
CH44  0.1U_0201_10V6K  [C_0201]  225.51 96.21 0 top
CH45  22U_0603_6.3V6M  [C_0603]  213.28 91.51 180 bottom
CH46  1U_0201_6.3V6M  [C_0201]  216.02 89.89 90 top
CH47  22U_0603_6.3V6M  [C_0603]  234.69 89.8 180 top
CH62  0.1U_0201_10V6K  [C_0201]  233.15 101.39 180 top
CH63  0.1U_0201_10V6K  [C_0201]  241.66 115.71 0 bottom
CH64  0.1U_0201_10V6K  [C_0201]  233.27 97.96 180 top
CH65  0.1U_0201_10V6K  [C_0201]  242.91 113.17 0 top
CH66  0.1U_0201_10V6K  [C_0201]  231.84 97.51 90 top
CH67  0.1U_0201_10V6K  [C_0201]  217.58 113.55 180 top
CH68  0.1U_0201_10V6K  [C_0201]  240.24 114.06 0 bottom
CH266  0.01U_0402_25V7K~D  [C_0402]  239.77 112.8 270 top
CH267  1U_0201_6.3V6M  [C_0201]  243.42 89.8 0 bottom
CH268  47P_0402_50V8J  [C_0402]  218.49 123.64 0 top
CH270  0.1U_0201_10V6K  [C_0201]  254.06 92.7 270 top
CH321  33P_0402_50V8J  [C_0402]  251.65 91.02 270 top
CH322  33P_0402_50V8J  [C_0402]  251.14 108.39 90 bottom
CH323  4.7U_0402_6.3V6M  [C_0402]  217.62 114.37 180 top
CH324  22U_0603_6.3V6M  [C_0603]  243.77 87.01 0 bottom
CH340  0.1U_0402_25V6K  [C_0402]  246.87 120.53 0 top
CH341  0.033U_0402_16V7  [C_0402]  238.95 115.63 90 bottom
CH342  0.033U_0402_16V7  [C_0402]  240.58 116.28 0 top
CH343  0.033U_0402_16V7  [C_0402]  236.1 115.45 180 top
CH344  0.033U_0402_16V7  [C_0402]  238.13 119.45 180 top
CH345  0.033U_0402_16V7  [C_0402]  234.89 117.99 180 bottom
CH346  0.033U_0402_16V7  [C_0402]  237.75 119.45 180 bottom
CH347  0.033U_0402_16V7  [C_0402]  237.36 117.03 90 top
CH348  0.033U_0402_16V7  [C_0402]  234.32 115.45 180 top
CH349  22U_0603_6.3V6M  [C_0603]  211.45 92.28 90 top
CH350  22U_0603_6.3V6M  [C_0603]  243.77 88.21 0 bottom
CH550  0.1U_0201_10V6K  [C_0201]  212.06 101.36 180 top
CH551  0.1U_0201_10V6K  [C_0201]  212.06 100.72 180 top
CH552  0.1U_0201_10V6K  [C_0201]  226.82 130.99 270 top
CH553  0.1U_0201_10V6K  [C_0201]  238.27 107.9 0 top
CH554  4.7U_0201_6.3V6M  [C_0201]  218.87 95.69 90 top
CH555  1U_0201_6.3V6M  [C_0201]  243.42 89.16 0 bottom
CH556  0.1U_0201_10V6K  [C_0201]  242.25 108.32 270 top
CH558  0.1U_0201_10V6K  [C_0201]  235.33 119.3 270 top
CH559  4.7U_0402_6.3V6M  [C_0402]  216.72 115.25 90 top
CI1  100U_A_6.3VM_R70M  [C_A]  19.87 96.63 270 bottom
CI3  0.1U_0201_10V6K  [C_0201]  21.78 95.07 270 bottom
CI4  0.1U_0402_25V6  [C_0402]  21 90.88 0 bottom
CI5  0.1U_0402_25V6  [C_0402]  21 89.99 0 bottom
CI6  10U_0603_10V6M  [C_0603]  27.68 89.23 90 bottom
CI7  0.1U_0201_10V6K  [C_0201]  26.79 89.13 90 bottom
CI8  100U_A_6.3VM_R70M  [C_A]  300.5 47.95 180 top
CI9  100P_0402_50V8J  [C_0402]  296.22 50.8 90 top
CI10  0.1U_0201_10V6K  [C_0201]  300.6 45.83 270 top
CI11  10U_0603_10V6M  [C_0603]  295.08 50.81 90 top
CI12  0.1U_0201_10V6K  [C_0201]  296.98 51.09 90 top
CI13  0.1U_0402_25V6  [C_0402]  296.91 68.3 180 bottom
CI14  100U_A_6.3VM_R70M  [C_A]  297.39 62.82 90 bottom
CI16  0.1U_0402_25V6  [C_0402]  296.91 67.38 180 bottom
CI17  0.1U_0201_10V6K  [C_0201]  299.32 61.99 270 bottom
CI19  0.1U_0201_10V6K  [C_0201]  291.14 71.39 180 top
CI27  0.1U_0402_25V6  [C_0402]  296.29 45.95 180 bottom
CI28  0.1U_0402_25V6  [C_0402]  296.29 45.06 180 bottom
CI31  10U_0402_6.3V6M  [C_0402]  291.31 72.16 180 top
CI32  150U_B2_6.3VM_R35M  [C_B2-NPM]  297.39 63.14 270 bottom
CI33  47U_0603_6.3V6M  [C_0603]  292.59 73.62 90 top
CI34  47U_0603_6.3V6M  [C_0603]  291.38 73.62 90 top
CI43  12P_0402_50V8J  [C_0402]  296.3 73.92 180 top
CI44  68P_0402_50V8J  [C_0402]  297.59 72.73 0 top
CI45  12P_0402_50V8J  [C_0402]  22.41 87.02 90 bottom
CI46  68P_0402_50V8J  [C_0402]  21.39 87.02 90 bottom
CI47  12P_0402_50V8J  [C_0402]  301.37 45.93 270 top
CI48  68P_0402_50V8J  [C_0402]  298.47 45.9 180 top
CI49  0.1U_0402_10V7K  [C_0402]  80.76 100.73 180 top
CI50  0.01UF_0402_25V7K  [C_0402]  73.48 95.83 180 top
CI51  0.1U_0402_10V7K  [C_0402]  79.85 98.88 0 top
CI52  .1U_0402_16V7K  [C_0402]  79.34 103.06 90 top
CI53  0.1U_0402_10V7K  [C_0402]  80.76 99.84 180 top
CI54  0.1U_0402_10V7K  [C_0402]  79.85 97.99 0 top
CI103  150U_B2_6.3VM_R35M  [C_B2-NPM]  19.87 96.24 90 bottom
CI104  150U_B2_6.3VM_R35M  [C_B2-NPM]  300.19 47.95 0 top
CL1  0.1U_0402_25V6  [C_0402]  269.79 116.05 0 top
CL2  0.1U_0402_25V6  [C_0402]  269.79 115.16 0 top
CL3  0.1U_0201_10V6K  [C_0201]  280.4 115.18 45 top
CL4  10U_0603_10V6M  [C_0603]  276.56 105.47 270 top
CL5  0.1U_0402_25V6  [C_0402]  269.79 114.21 0 top
CL6  0.1U_0402_25V6  [C_0402]  269.79 113.32 0 top
CL7  0.1U_0201_10V6K  [C_0201]  277.17 117.96 90 top
CL8  0.1U_0201_10V6K  [C_0201]  280.88 112.28 0 top
CL9  0.1U_0201_10V6K  [C_0201]  280.09 108.62 90 top
CL10  0.1U_0201_10V6K  [C_0201]  280.25 108.02 0 top
CL11  0.1U_0201_10V6K  [C_0201]  271.77 116.77 90 top
CL12  22U_0603_6.3V6M  [C_0603]  271.2 111.6 180 top
CL13  27P_0402_50V8J  [C_0402]  279.21 106.4 180 top
CL14  27P_0402_50V8J  [C_0402]  280.07 106.4 0 top
CL16  0.1U_0201_10V6K  [C_0201]  287.75 99.51 180 bottom
CL17  0.1U_0201_10V6K  [C_0201]  287.75 102.5 180 bottom
CL18  470P_0402_50V7K  [C_0402]  295.07 115.02 90 top
CL19  0.1U_0201_10V6K  [C_0201]  295.84 115.25 90 top
CL20  0.1U_0201_10V6K  [C_0201]  287.75 105.48 180 bottom
CL21  0.1U_0201_10V6K  [C_0201]  287.75 108.47 180 bottom
CL22  10P_1808_3KV8J  [C_1808]  291.63 95.39 0 bottom
CL28  22U_0603_6.3V6M  [C_0603]  274.7 104.28 180 top
CL29  12P_0402_50V8J  [C_0402]  280.84 113.68 0 top
CL30  82P_0402_50V8J  [C_0402]  274.06 107.85 270 top
CLP1  -  [EMIST_SUL-12A2M_1P]  50.4 115.39 180 bottom
CLP2  -  [EMIST_SUL-12A2M_1P]  73.78 105.67 90 bottom
CLP3  -  [EMIST_SUL-12A2M_1P]  27.05 97.8 270 bottom
CLP4  -  [EMIST_SUL-12A2M_1P]  50.4 96.97 180 bottom
CMOS1  SHORT PADS~D  [SHORTPADS-NPM]  243.2 108.02 90 top
CN1  10U_0603_10V6M  [C_0603]  253.33 37.85 0 top
CN2  0.1U_0201_10V6K  [C_0201]  253.44 43.98 0 bottom
CN3  0.1U_0201_10V6K  [C_0201]  253.76 38.78 0 top
CN4  0.01UF_0402_25V7K  [C_0402]  247.08 36.62 180 top
CN5  0.01UF_0402_25V7K  [C_0402]  247.08 35.73 180 top
CN6  0.01UF_0402_25V7K  [C_0402]  247.27 34.59 180 top
CN7  0.01UF_0402_25V7K  [C_0402]  247.27 33.7 180 top
CN8  1000P_0402_50V7K  [C_0402]  252.66 35.55 270 top
CN9  0.1U_0201_10V6K  [C_0201]  251.9 35.51 270 top
CN10  0.1U_0201_10V6K  [C_0201]  250.12 35.89 270 top
CN11  0.1U_0201_10V6K  [C_0201]  250.69 35.89 270 top
CN12  0.01UF_0402_25V7K  [C_0402]  237.98 36.87 0 top
CN13  0.01UF_0402_25V7K  [C_0402]  237.98 35.98 0 top
CN14  0.01UF_0402_25V7K  [C_0402]  237.98 35.03 0 top
CN15  0.01UF_0402_25V7K  [C_0402]  237.98 34.14 0 top
CN16  0.01UF_0402_25V7K  [C_0402]  245.04 31.84 270 top
CN17  0.1U_0201_10V6K  [C_0201]  240.82 38.78 180 top
CN60  0.01U_0402_16V7K  [C_0402]  278.27 22.17 180 top
CN61  0.1U_0402_10V7K  [C_0402]  278.28 21.23 180 top
CN62  0.1U_0402_10V7K  [C_0402]  283.25 21.21 0 top
CN63  22U_0603_6.3V6M  [C_0603]  278.19 23.25 180 top
CN64  22U_0603_6.3V6M  [C_0603]  281.81 23.38 180 top
CN65  0.22U_0402_10V6K  [C_0402]  280.54 28.33 90 top
CN66  0.22U_0402_10V6K  [C_0402]  279.59 28.32 90 top
CN67  0.22U_0402_10V6K  [C_0402]  277.68 28.32 90 top
CN68  0.22U_0402_10V6K  [C_0402]  276.73 28.33 90 top
CN69  0.22U_0402_10V6K  [C_0402]  274.51 28.32 90 top
CN70  0.22U_0402_10V6K  [C_0402]  273.55 28.33 90 top
CN71  0.22U_0402_10V6K  [C_0402]  271.46 28.32 90 top
CN72  0.22U_0402_10V6K  [C_0402]  270.44 28.32 90 top
CN77  22U_0603_6.3V6M  [C_0603]  265.11 25.54 0 top
CN80  0.01U_0402_16V7K  [C_0402]  281.84 22.11 180 top
CN81  0.01U_0402_16V7K  [C_0402]  281.83 21.16 180 top
CN82  0.01U_0402_16V7K  [C_0402]  265.6 23.51 0 top
CN84  0.01U_0402_16V7K  [C_0402]  265.6 22.55 0 top
CN86  0.1U_0402_10V7K  [C_0402]  265.6 24.46 0 top
CR1  4.7U_0402_6.3V6M  [C_0402]  294.18 28.33 0 top
CR2  0.1U_0201_10V6K  [C_0201]  294.15 27.57 0 top
CR3  0.1U_0201_10V6K  [C_0201]  293.5 19.52 0 top
CR4  10U_0402_6.3V6M  [C_0402]  293.27 18.76 0 top
CR5  4.7U_0402_10V6M  [C_0402]  292.43 19.12 180 top
CR6  0.1U_0201_10V6K  [C_0201]  295.52 19.46 180 top
CR7  0.1U_0201_10V6K  [C_0201]  295.52 18.89 180 top
CR11  0.1U_0402_25V6  [C_0402]  288.04 25.05 0 top
CR12  0.1U_0402_25V6  [C_0402]  288.04 24.16 0 top
CR13  0.1U_0402_25V6  [C_0402]  285.05 22.83 0 top
CR14  0.1U_0402_25V6  [C_0402]  285.05 21.94 0 top
CR15  1U_0201_10V6M  [C_0201]  296.18 26.85 0 top
CR17  0.1U_0201_10V6K  [C_0201]  302.72 20.96 270 top
CR18  4.7U_0402_10V6M  [C_0402]  301.96 21.25 270 top
CR19  0.1U_0201_10V6K  [C_0201]  302.7 25.58 270 top
CR20  4.7U_0402_10V6M  [C_0402]  301.94 25.74 270 top
CR21  5P_0402_50V8C  [C_0402]  298.08 21 270 top
CR22  1U_0201_10V6M  [C_0201]  297.22 22.64 0 top
CR25  12P_0402_50V8J  [C_0402]  288.04 27.02 0 top
CR26  82P_0402_50V8J  [C_0402]  288.04 26.13 0 top
CR27  12P_0402_50V8J  [C_0402]  291.42 28.08 90 top
CR28  82P_0402_50V8J  [C_0402]  290.46 28.08 90 top
CT1  0.1U_0201_10V6K  [C_0201]  36.85 125.36 0 bottom
CT2  0.22U_0201_6.3V6K  [C_0201]  46.99 99.51 90 bottom
CT3  0.22U_0201_6.3V6K  [C_0201]  47.56 99.51 90 bottom
CT4  0.22U_0201_6.3V6K  [C_0201]  44.45 99.51 90 bottom
CT5  0.22U_0201_6.3V6K  [C_0201]  45.02 99.51 90 bottom
CT6  0.22U_0201_6.3V6K  [C_0201]  45.72 100.09 270 bottom
CT7  0.22U_0201_6.3V6K  [C_0201]  46.29 100.09 270 bottom
CT8  0.22U_0201_6.3V6K  [C_0201]  43.75 100.09 270 bottom
CT9  0.22U_0201_6.3V6K  [C_0201]  43.18 100.09 270 bottom
CT10  0.1U_0201_10V6K  [C_0201]  49.57 110.53 180 bottom
CT11  0.1U_0201_10V6K  [C_0201]  49.57 109.96 180 bottom
CT12  0.1U_0201_10V6K  [C_0201]  49.57 109.26 180 bottom
CT13  0.1U_0201_10V6K  [C_0201]  49.57 108.69 180 bottom
CT14  0.1U_0201_10V6K  [C_0201]  49.57 107.99 180 bottom
CT15  0.1U_0201_10V6K  [C_0201]  49.57 107.42 180 bottom
CT16  0.1U_0201_10V6K  [C_0201]  49.57 106.15 180 bottom
CT17  0.1U_0201_10V6K  [C_0201]  49.57 106.72 180 bottom
CT18  0.1U_0201_10V6K  [C_0201]  52.68 107.42 180 top
CT19  0.1U_0201_10V6K  [C_0201]  52.68 107.99 180 top
CT20  27P_0402_50V8J  [C_0402]  33.57 96.65 0 bottom
CT21  27P_0402_50V8J  [C_0402]  33.57 98.43 0 bottom
CT25  1U_0201_6.3V6M  [C_0201]  41.69 106.67 0 top
CT26  1U_0201_6.3V6M  [C_0201]  40.97 109.34 90 top
CT27  1U_0201_6.3V6M  [C_0201]  41.75 108.51 0 top
CT28  1U_0201_6.3V6M  [C_0201]  42.2 109.9 0 top
CT29  1U_0201_6.3V6M  [C_0201]  46.8 105.61 270 top
CT30  1U_0201_6.3V6M  [C_0201]  46.22 105.62 270 top
CT31  1U_0201_6.3V6M  [C_0201]  44.86 105.84 180 top
CT32  1U_0201_6.3V6M  [C_0201]  43.03 105.21 180 top
CT33  1U_0201_6.3V6M  [C_0201]  43.65 104.75 0 top
CT34  1U_0201_6.3V6M  [C_0201]  42.63 101.64 0 top
CT35  1U_0201_6.3V6M  [C_0201]  42.63 102.22 0 top
CT36  1U_0201_6.3V6M  [C_0201]  41.56 101.64 180 top
CT37  1U_0201_6.3V6M  [C_0201]  41.56 102.22 180 top
CT38  1U_0201_6.3V6M  [C_0201]  44.16 108.69 0 top
CT39  1U_0201_6.3V6M  [C_0201]  42.97 107.94 180 top
CT40  1U_0201_6.3V6M  [C_0201]  43.5 107.21 270 top
CT41  1U_0201_6.3V6M  [C_0201]  44.17 109.25 0 top
CT42  1U_0201_6.3V6M  [C_0201]  39.03 109.79 180 top
CT43  1U_0201_6.3V6M  [C_0201]  39.4 108.58 180 top
CT44  10U_0402_6.3V6M  [C_0402]  37.66 110.63 270 top
CT45  10U_0402_6.3V6M  [C_0402]  36.77 110.67 270 top
CT46  10U_0402_6.3V6M  [C_0402]  37.78 111.6 90 top
CT47  10U_0402_6.3V6M  [C_0402]  36.89 111.6 90 top
CT48  1U_0201_6.3V6M  [C_0201]  37.78 107.76 90 top
CT49  1U_0201_6.3V6M  [C_0201]  39.68 106.39 270 top
CT50  1U_0201_6.3V6M  [C_0201]  37.78 107.14 270 top
CT51  1U_0201_6.3V6M  [C_0201]  37.24 105.39 0 top
CT52  1U_0201_6.3V6M  [C_0201]  37.24 105.96 0 top
CT53  1U_0201_6.3V6M  [C_0201]  37.21 107.76 90 top
CT54  1U_0201_6.3V6M  [C_0201]  37.21 107.14 270 top
CT55  47U_0603_6.3V6M  [C_0603]  30.36 113.54 180 bottom
CT56  47U_0603_6.3V6M  [C_0603]  30.36 112.33 180 bottom
CT57  47U_0603_6.3V6M  [C_0603]  30.36 111.13 180 bottom
CT59  10U_0402_6.3V6M  [C_0402]  37.15 102.63 270 top
CT60  10U_0402_6.3V6M  [C_0402]  35.68 102.64 270 top
CT61  1U_0201_6.3V6M  [C_0201]  39.89 107.12 0 top
CT62  1U_0201_6.3V6M  [C_0201]  38.28 104.71 180 top
CT63  1U_0201_6.3V6M  [C_0201]  40.24 103.94 180 top
CT64  1U_0201_6.3V6M  [C_0201]  40.24 105.22 180 top
CT67  1U_0201_6.3V6M  [C_0201]  48 100.44 270 top
CT68  47U_0603_6.3V6M  [C_0603]  48.96 100.75 270 top
CT69  47U_0603_6.3V6M  [C_0603]  50.23 100.75 270 top
CT70  .1U_0402_16V7K  [C_0402]  63.38 98.18 180 bottom
CT71  2.2U_0402_25V6K  [C_0402]  58.76 106.11 180 bottom
CT72  2.2U_0402_25V6K  [C_0402]  62.35 104.58 90 top
CT73  2.2U_0402_25V6K  [C_0402]  60.09 110.75 180 bottom
CT74  10U_0402_6.3V6M  [C_0402]  57.29 104.15 180 top
CT75  22U_0603_10V6M  [C_0603]  69.85 106.37 0 bottom
CT76  22U_0603_10V6M  [C_0603]  69.85 105.17 0 bottom
CT77  22U_0603_10V6M  [C_0603]  69.82 103.92 0 bottom
CT78  22U_0603_10V6M  [C_0603]  69.85 102.44 0 top
CT80  0.1U_0201_10V6K  [C_0201]  57.06 109.67 0 bottom
CT81  0.1U_0201_10V6K  [C_0201]  57.06 110.3 0 bottom
CT82  1U_0402_25V6K  [C_0402]  65.41 122.31 180 top
CT83  1U_0201_10V6M  [C_0201]  59.9 109.16 180 bottom
CT84  10U_0402_6.3V6M  [C_0402]  58.49 107.64 180 bottom
CT85  220P_0402_50V8J  [C_0402]  68.37 112.72 0 bottom
CT86  220P_0402_50V8J  [C_0402]  66.61 113.41 90 bottom
CT87  0.22U_0402_16V7K  [C_0402]  64.7 109.6 0 top
CT88  0.1U_0201_10V6K  [C_0201]  61.27 124.43 90 top
CT89  1U_0201_10V6M  [C_0201]  59.56 124.08 90 top
CT90  1U_0201_10V6M  [C_0201]  57.17 124.66 0 top
CT91  2.2U_0402_10V6M  [C_0402]  58.32 119.04 0 top
CT92  0.1U_0402_25V6K  [C_0402]  58.32 118.16 0 top
CT93  1U_0201_10V6M  [C_0201]  63.75 121.89 90 top
CT94  1U_0402_25V6K  [C_0402]  65.67 112.53 180 top
CT95  0.22U_0201_25V6K  [C_0201]  14.39 103.16 180 bottom
CT96  0.22U_0201_25V6K  [C_0201]  14.39 103.8 180 bottom
CT97  0.22U_0201_25V6K  [C_0201]  15.09 107.07 180 top
CT98  0.22U_0201_25V6K  [C_0201]  15.09 106.44 180 top
CT99  0.47U_0201_25V  [C_0201]  10.66 105.45 90 top
CT100  0.47U_0201_25V  [C_0201]  10.66 107.35 90 top
CT101  0.47U_0201_25V  [C_0201]  11.23 107.94 270 top
CT102  0.47U_0201_25V  [C_0201]  11.3 106.03 270 top
CT123  0.22U_0201_6.3V6K  [C_0201]  41.91 99.51 90 bottom
CT124  0.22U_0201_6.3V6K  [C_0201]  42.48 99.51 90 bottom
CT125  0.22U_0201_6.3V6K  [C_0201]  39.37 99.51 90 bottom
CT126  0.22U_0201_6.3V6K  [C_0201]  39.94 99.51 90 bottom
CT127  0.22U_0201_6.3V6K  [C_0201]  40.64 100.09 270 bottom
CT128  0.22U_0201_6.3V6K  [C_0201]  41.21 100.09 270 bottom
CT129  0.22U_0201_6.3V6K  [C_0201]  38.1 100.09 270 bottom
CT130  0.22U_0201_6.3V6K  [C_0201]  38.67 100.09 270 bottom
CT178  0.1U_0201_10V6K  [C_0201]  47.66 107.16 180 top
CT179  0.1U_0201_10V6K  [C_0201]  49.57 102.34 180 bottom
CT180  0.1U_0201_10V6K  [C_0201]  49.57 103.61 180 bottom
CT181  0.1U_0201_10V6K  [C_0201]  49.57 101.07 180 bottom
CT182  0.1U_0201_10V6K  [C_0201]  49.57 101.64 180 bottom
CT183  0.1U_0201_10V6K  [C_0201]  49.57 104.18 180 bottom
CT184  0.1U_0201_10V6K  [C_0201]  47.66 106.59 180 top
CT185  0.1U_0201_10V6K  [C_0201]  49.57 102.91 180 bottom
CT186  0.1U_0201_10V6K  [C_0201]  49.57 105.45 180 bottom
CT187  0.1U_0201_10V6K  [C_0201]  49.57 104.88 180 bottom
CT189  12P_0402_50V8J  [C_0402]  19.88 97.86 180 top
CT190  82P_0402_50V8J  [C_0402]  19.88 96.97 180 top
CT237  0.1U_0201_10V6K  [C_0201]  29.01 118.92 270 bottom
CT326  0.33U_0201_25V6K  [C_0201]  14.39 103.16 180 top
CT327  0.33U_0201_25V6K  [C_0201]  14.39 103.8 180 top
CT328  0.33U_0201_25V6K  [C_0201]  15.09 107.07 180 bottom
CT329  0.33U_0201_25V6K  [C_0201]  15.09 106.44 180 bottom
CT360  0.1U_0201_10V6K  [C_0201]  29.77 125.24 270 bottom
CV1  0.1U_0402_25V6  [C_0402]  139.57 120.65 90 bottom
CV2  0.1U_0402_25V6  [C_0402]  140.52 120.64 90 bottom
CV3  0.1U_0402_25V6  [C_0402]  141.73 120.64 90 bottom
CV4  0.1U_0402_25V6  [C_0402]  142.62 120.64 90 bottom
CV5  0.1U_0402_25V6  [C_0402]  143.7 120.64 90 bottom
CV6  0.1U_0402_25V6  [C_0402]  144.59 120.64 90 bottom
CV8  100P_0201_25V7K~D  [C_0201]  146.21 135.39 180 top
CV9  100P_0201_25V7K~D  [C_0201]  146.21 134.82 180 top
CV10  100P_0201_25V7K~D  [C_0201]  141.79 131.24 270 top
CV11  0.1U_0402_50V7K  [C_0402]  133.54 130.59 270 top
CV12  0.1U_0201_10V6K  [C_0201]  141.16 131.24 270 top
CV13  1000P_0402_50V7K  [C_0402]  129.6 135.33 270 top
CV14  0.01U_0402_50V7K  [C_0402]  127.96 134.38 180 top
CV15  0.1U_0402_25V6  [C_0402]  134.6 136.28 0 top
CV16  10U_0603_10V6M  [C_0603]  143.63 131.9 270 top
CV17  0.01UF_0402_25V7K  [C_0402]  145.98 134.07 270 top
CV18  12P_0402_50V8J  [C_0402]  125.82 131.92 0 top
CV19  82P_0402_50V8J  [C_0402]  125.82 131.03 0 top
CV20  12P_0402_50V8J  [C_0402]  143.07 134.67 90 top
CV21  82P_0402_50V8J  [C_0402]  143.95 134.67 90 top
CV22  12P_0402_50V8J  [C_0402]  130.7 130.79 90 top
CV23  82P_0402_50V8J  [C_0402]  131.58 130.79 90 top
CV24  12P_0402_50V8J  [C_0402]  135.45 130.57 270 top
CV25  82P_0402_50V8J  [C_0402]  134.56 130.57 270 top
CV31  0.1U_0201_10V6K  [C_0201]  288.12 90.12 0 top
CV32  0.1U_0201_10V6K  [C_0201]  288.14 89.5 0 top
CV33  0.1U_0201_10V6K  [C_0201]  288.18 88.34 0 top
CV34  0.1U_0201_10V6K  [C_0201]  288.18 87.77 0 top
CV35  0.1U_0201_10V6K  [C_0201]  288.18 86.5 0 top
CV36  0.1U_0201_10V6K  [C_0201]  288.18 85.93 0 top
CV37  0.1U_0201_10V6K  [C_0201]  288.12 84.72 0 top
CV38  0.1U_0201_10V6K  [C_0201]  288.12 84.15 0 top
CV39  18P_0201_25V8J  [C_0201]  294.95 78.73 270 top
CV40  0.1U_0201_10V6K  [C_0201]  303.53 81.46 270 top
CV41  10U_0603_10V6M  [C_0603]  302.57 82.31 270 top
CV42  0.1U_0402_25V6  [C_0402]  299.63 90.89 270 bottom
CV43  0.1U_0402_25V6  [C_0402]  299.65 87.27 270 bottom
CV44  0.1U_0402_25V6  [C_0402]  298.64 87.27 270 bottom
CV45  0.1U_0402_25V6  [C_0402]  296.86 82.45 270 bottom
CV46  0.01UF_0402_25V7K  [C_0402]  295.97 82.45 270 bottom
CV47  0.1U_0402_25V6  [C_0402]  295.91 84.96 90 bottom
CV48  0.01UF_0402_25V7K  [C_0402]  297.62 87.27 270 bottom
CV601  0.1U_0201_10V6K  [C_0201]  286.72 93.36 0 top
CV602  0.1U_0201_10V6K  [C_0201]  286.72 93.93 0 top
CV603  0.1U_0201_10V6K  [C_0201]  288.5 93.36 0 top
CV604  0.1U_0201_10V6K  [C_0201]  288.5 93.93 0 top
CV605  1U_0201_10V6M  [C_0201]  288.83 91.13 180 top
CV606  18P_0402_50V8J  [C_0402]  291.27 96.2 90 top
CV607  18P_0402_50V8J  [C_0402]  291.27 95.02 270 top
CV608  0.1U_0402_25V6  [C_0402]  297.24 84.07 90 bottom
CV609  0.1U_0402_25V6  [C_0402]  297.54 88.21 0 bottom
CV610  0.01UF_0402_25V7K  [C_0402]  301.46 86.35 180 bottom
CV611  0.1U_0402_25V6  [C_0402]  298.74 90.89 270 bottom
CV612  0.01UF_0402_25V7K  [C_0402]  297.08 90.81 180 bottom
CV613  0.01UF_0402_25V7K  [C_0402]  297.54 89.1 0 bottom
CV614  0.1U_0402_25V6  [C_0402]  283.87 90.62 180 bottom
CV615  0.01UF_0402_25V7K  [C_0402]  283.87 89.73 180 bottom
CV616  0.01UF_0402_25V7K  [C_0402]  283.85 91.58 180 bottom
CV617  0.1U_0402_25V6  [C_0402]  291.32 91.46 90 bottom
CV618  0.1U_0402_25V6  [C_0402]  289.54 91.46 90 bottom
CV619  0.01UF_0402_25V7K  [C_0402]  292.21 91.46 90 bottom
CV620  0.47U_0402_25V6K  [C_0402]  301.56 84.07 90 bottom
CV621  0.47U_0402_25V6K  [C_0402]  302.89 88.54 270 bottom
